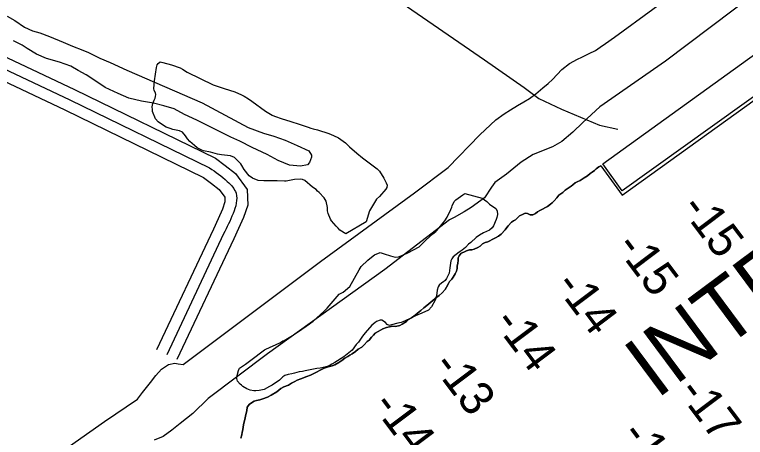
# Model space of a CAD drawing. Extents: x 3683613 to 3738215, y 469626 to 495384.
# Drawn here: x 3688948 to 3689919, y 488310 to 488872 of the extents above; entities that cross this region are included whole.
import ezdxf

# ---------------------------------------------------------------- set-up
doc = ezdxf.new("R2010")
doc.units = 0
for name, color, linetype in [('V-CHAN-DOCK', 7, 'Continuous'), ('V-LEVE-TOET', 7, 'Continuous'), ('V-RIVR-IDEN', 7, 'Continuous'), ('V-ROAD-CNTR', 7, 'Continuous'), ('V-SITE-VEGE', 7, 'Continuous'), ('V-TOPO-SHOR', 7, 'Continuous'), ('V-TOPO-SPOT', 7, 'Continuous')]:
    doc.layers.add(name, color=color, linetype=linetype)

msp = doc.modelspace()

# ---------------------------------------------------------------- linework, layer by layer
at = {"layer": 'V-CHAN-DOCK'}
msp.add_lwpolyline([(3689729.15, 488673.5), (3690051.71, 488906.29), (3690078.78, 488869.56), (3689754.74, 488637.61), (3689729.15, 488673.5)], dxfattribs=at)
at = {"layer": 'V-LEVE-TOET'}
for points in [[(3688803.07, 488145.2), (3689067.59, 488331.33), (3689111.3, 488360.98), (3689118.03, 488369.9), (3689128.56, 488382.87), (3689135.72, 488392.43), (3689143.31, 488400.73), (3689152.6, 488406.92), (3689161.06, 488408.44), (3689165.3, 488407.61), (3689172.08, 488407.01), (3689354.44, 488543.83), (3689479.19, 488635.06), (3689523.94, 488668.31), (3689566.1, 488711.93), (3689586.98, 488731.72), (3689598.16, 488740.03), (3689606.61, 488744.95), (3689616.12, 488750.92), (3689624.35, 488755.62), (3689631.96, 488760.31), (3689640.4, 488766.28), (3689649.68, 488774.37), (3689656.86, 488780.12), (3689662.34, 488785.45), (3689674.78, 488798.64), (3689684.91, 488806.52), (3689695.47, 488812.5), (3689701.39, 488815.28), (3689711.32, 488819.98), (3689719.56, 488824.05), (3689725.68, 488828.31), (3689732.86, 488833.43), (3689744.9, 488841.53), (3689897.29, 488953.44)], [(3689994.12, 488947.11), (3689812.61, 488809.86), (3689725.2, 488749.1), (3689702.85, 488728.23), (3689689.56, 488715.68), (3689674.8, 488703.11), (3689662.54, 488695.85), (3689636.54, 488685.99), (3689620.7, 488675.54), (3689601.5, 488659.56), (3689585.88, 488648.69), (3689581.25, 488642.31), (3689572.21, 488628.08), (3689554.26, 488615.5), (3689545.18, 488609.74), (3689531.66, 488602.05), (3689525.75, 488599.06), (3689439.64, 488533.21), (3689283.85, 488420.87), (3689205.33, 488361.62), (3689184.67, 488341.83), (3689168, 488328.41), (3689157.03, 488319.46), (3689145.42, 488311.36), (3689133.58, 488306.43)]]:
    msp.add_lwpolyline(points, dxfattribs=at)
at = {"layer": 'V-ROAD-CNTR'}
for points in [[(3689142.23, 489278.29), (3689162.29, 489246.61), (3689268.46, 489096.31), (3689365.64, 488967.98), (3689394.38, 488935.92), (3689455.59, 488891.94), (3689572.03, 488811.36), (3689624.73, 488774.96), (3689644.49, 488760.23), (3689674.42, 488746.17), (3689724.72, 488724.8), (3689749.31, 488719.62)], [(3687694.8, 489100.44), (3687788.84, 489167.94), (3687806.27, 489176.37), (3687846.67, 489194.95), (3687889.36, 489212.36), (3687944.11, 489222.38), (3687999.07, 489216.94), (3688049.59, 489205.26), (3688098.64, 489190.05), (3688147.84, 489171.94), (3688197.16, 489153.78), (3688663.75, 488944.15), (3689027.79, 488771.96), (3689214.82, 488680.9), (3689227.8, 488671.05), (3689241.34, 488660.78), (3689257.09, 488639.36), (3689257.63, 488618.59), (3689252.22, 488602.03), (3689245.6, 488587.64), (3689239.31, 488573.98), (3689163.65, 488413.54)], [(3688191.29, 489139.97), (3688657.47, 488930.53), (3689021.3, 488758.43)], [(3688758.88, 488865.97), (3689014.81, 488744.91), (3689199.03, 488655.22), (3689209.67, 488647.15), (3689219.74, 488639.51), (3689227.35, 488629.17), (3689227.51, 488622.99), (3689224.24, 488612.99), (3689218.35, 488600.18), (3689212.12, 488586.65), (3689136.52, 488426.33)], [(3689021.3, 488758.43), (3689206.93, 488668.06)], [(3689225.71, 488580.31), (3689150.08, 488419.93)]]:
    msp.add_lwpolyline(points, dxfattribs=at)
msp.add_spline([(3689206.93, 488668.06), (3689230.54, 488650.14), (3689242.22, 488634.26), (3689238.23, 488607.51), (3689225.71, 488580.31)], degree=3, dxfattribs=at)
at = {"layer": 'V-SITE-VEGE'}
for points in [[(3689303.27, 488732.95), (3689313.45, 488730.04), (3689327.45, 488725.86), (3689337.85, 488722.1), (3689341.45, 488720.64), (3689344.42, 488720.01), (3689350.15, 488718.35), (3689365.42, 488713.54), (3689371.57, 488711.24), (3689378.16, 488707.89), (3689387.72, 488701.15), (3689393.04, 488696.09), (3689402.39, 488687.66), (3689410.05, 488681.56), (3689429.39, 488666.82), (3689432.58, 488663.66), (3689438.35, 488654.37), (3689440.48, 488649.93), (3689441.76, 488648.24), (3689442.84, 488644.86), (3689442.21, 488641.89), (3689441.17, 488639.55), (3689432.74, 488630.2), (3689428.73, 488626.36), (3689419.48, 488611.07), (3689415.1, 488596.44), (3689387.85, 488580.21), (3689380, 488585.26), (3689377.87, 488587.79), (3689375.1, 488590.74), (3689369.14, 488597.49), (3689367.43, 488600.03), (3689364.43, 488607.22), (3689363.78, 488611.03), (3689363.76, 488615.26), (3689361.81, 488623.72), (3689359.04, 488628.16), (3689352.44, 488635.33), (3689350.31, 488637.23), (3689348.4, 488639.12), (3689343.93, 488642.49), (3689333.52, 488651.13), (3689330.33, 488652.59), (3689328, 488653.22), (3689319.74, 488652.76), (3689313.39, 488651.24), (3689308.95, 488650.59), (3689306.62, 488650.58), (3689296.66, 488650.96), (3689283.75, 488650.9), (3689278.87, 488650.66), (3689271.67, 488651.48), (3689263.82, 488654.41), (3689259.57, 488657.35), (3689253.18, 488666), (3689249.97, 488671.28), (3689248.69, 488673.18), (3689242.95, 488679.3), (3689240.18, 488681.62), (3689234.88, 488683.92), (3689223.01, 488685.35), (3689217.71, 488686.38), (3689208.17, 488688.88), (3689198.84, 488690.74), (3689196.72, 488691.58), (3689190.77, 488694.73), (3689187.16, 488697.68), (3689180.78, 488703.16), (3689177.58, 488706.74), (3689175.02, 488710.75), (3689170.98, 488715.61), (3689166.95, 488717.07), (3689158.25, 488718.94), (3689154.65, 488720.19), (3689149.55, 488722.29), (3689141.7, 488727.12), (3689138.72, 488729.22), (3689135.1, 488733.02), (3689131.25, 488742.74), (3689131.02, 488745.71), (3689130.58, 488749.31), (3689131.62, 488753.55), (3689133.5, 488757.79), (3689134.97, 488760.55), (3689135.39, 488762.67), (3689135.59, 488765.43), (3689135.15, 488767.76), (3689133.45, 488770.71), (3689132.8, 488773.25), (3689134.02, 488783.64), (3689136.48, 488801.23), (3689137.31, 488804.83), (3689138.57, 488806.53), (3689141.53, 488809.09), (3689144.92, 488807.83), (3689156.37, 488804.92), (3689168.04, 488800.74), (3689171.23, 488799.06), (3689177.38, 488795.27), (3689211.77, 488778.49), (3689226.41, 488773.48)], [(3689226.41, 488773.48), (3689240.41, 488768.88), (3689249.54, 488764.9), (3689252.94, 488763.22), (3689258.88, 488759.65), (3689263.13, 488756.7), (3689281.2, 488743.44), (3689290.12, 488737.98), (3689293.09, 488736.51), (3689303.27, 488732.95)], [(3689497.62, 488479.06), (3689488.74, 488474.99), (3689480.5, 488471.35), (3689474.16, 488468.36), (3689466.97, 488464.73), (3689463.8, 488463.44), (3689461.26, 488462.58), (3689457.24, 488461.71), (3689448.57, 488459.56), (3689446.03, 488458.7), (3689443.06, 488459.96), (3689440.5, 488462.48), (3689435.83, 488465.64), (3689433.5, 488465.84), (3689428.85, 488464.12), (3689426.32, 488462.42), (3689422.31, 488459.01), (3689413.67, 488448.81), (3689410.3, 488444.34), (3689404.62, 488436.48), (3689401.88, 488433.29), (3689396.41, 488425.85), (3689385.44, 488417.11), (3689373.19, 488409.65), (3689369.6, 488407.3), (3689366, 488405.17), (3689360.3, 488403.23), (3689353.95, 488401.93), (3689349.5, 488401.49), (3689345.06, 488400.83), (3689333.85, 488398.24), (3689330.46, 488397.59), (3689326.01, 488396.93), (3689319.67, 488395.42), (3689316.28, 488394.34), (3689311.21, 488393.47), (3689306.97, 488392.18), (3689304.44, 488390.48), (3689300.01, 488386.22), (3689290.3, 488379.61), (3689286.5, 488377.47), (3689279.31, 488373.84), (3689272.96, 488372.54), (3689268.31, 488371.88), (3689265.98, 488371.87), (3689260.89, 488372.69), (3689256.44, 488374.37), (3689251.34, 488377.52), (3689249.42, 488379.42), (3689247.72, 488380.68), (3689244.1, 488384.69), (3689243.03, 488388.07), (3689243.44, 488390.4), (3689245.31, 488399.1), (3689246.78, 488401.85), (3689254.8, 488407.4), (3689261.98, 488412.52), (3689279.92, 488426.37), (3689281.82, 488427.43), (3689300.21, 488435.78), (3689304.22, 488438.13), (3689306.12, 488438.78), (3689317.1, 488445.39), (3689325.13, 488450.72), (3689339.7, 488460.96), (3689344.55, 488464.58), (3689359.32, 488477.57), (3689363.32, 488481.82), (3689379.12, 488500.32), (3689382.5, 488502.25), (3689384.61, 488503.1), (3689393.48, 488510.34), (3689399.35, 488521.6), (3689405.66, 488532.43), (3689408.39, 488536.89), (3689417.25, 488545.4), (3689422.1, 488549.24), (3689425.9, 488552.65), (3689433.72, 488555.65), (3689439.02, 488553.98), (3689447.51, 488551.05), (3689450.48, 488550.43), (3689453.45, 488549.38), (3689457.89, 488550.04), (3689461.27, 488551.33), (3689470.36, 488555.18), (3689485.15, 488563.09), (3689494.64, 488572.66), (3689503.29, 488580.33), (3689507.3, 488583.52), (3689511.93, 488588.42), (3689517.41, 488595.01), (3689519.52, 488597.77), (3689522.67, 488602.44), (3689527.49, 488612.63), (3689528.75, 488615.82), (3689529.38, 488617.73), (3689531.68, 488623.24), (3689534.21, 488625.8), (3689543.5, 488632.19), (3689546.04, 488634.11)], [(3689546.04, 488634.11), (3689569.15, 488627.86), (3689575.1, 488623.23), (3689578.93, 488619.86), (3689587.22, 488614.18), (3689589.14, 488611.01), (3689589.37, 488606.14), (3689588.54, 488601.9), (3689587.71, 488599.36), (3689584.15, 488590.87), (3689582.46, 488588.53), (3689578.67, 488585.34), (3689570.85, 488581.7), (3689565.56, 488578.71), (3689560.92, 488575.51), (3689553.96, 488569.13), (3689551.01, 488566.57), (3689546.79, 488562.1), (3689544.89, 488560.4), (3689542.57, 488558.9), (3689538.35, 488555.92), (3689530.33, 488549.74), (3689528.64, 488547.19), (3689527.39, 488544.43), (3689525.95, 488535.11), (3689525.14, 488528.11), (3689521.56, 488521.11), (3689519.89, 488518.35), (3689517.77, 488516.64), (3689515.66, 488515.15), (3689511.87, 488512.17), (3689510.6, 488510.25), (3689509.14, 488505.59), (3689508.33, 488497.96), (3689506.45, 488492.23), (3689501.83, 488483.53), (3689497.62, 488479.06)]]:
    msp.add_lwpolyline(points, dxfattribs=at)
at = {"layer": 'V-TOPO-SHOR'}
for points in [[(3688938.41, 488869.51), (3688948.6, 488863.62), (3688961.35, 488855), (3688971.75, 488850.18), (3688981.51, 488847.26), (3688994.45, 488842.45), (3689012.7, 488834.91), (3689025.01, 488829.88), (3689038.8, 488824.44), (3689046.23, 488821.29), (3689061.3, 488813.95), (3689075.09, 488808.08), (3689097.17, 488797.6), (3689197.13, 488754.22), (3689258.28, 488721.88), (3689278.65, 488714.35), (3689292.44, 488710.18), (3689307.5, 488704.74), (3689323.42, 488697.83), (3689338.91, 488690.7), (3689342.54, 488684.79), (3689342.55, 488682.24), (3689339.83, 488675.24), (3689337.09, 488672.27), (3689327.99, 488670.32), (3689313.16, 488671.73), (3689298.09, 488678.01), (3689283.65, 488685.78), (3689263.49, 488695.01), (3689247.35, 488703.41), (3689235.47, 488708.86), (3689212.96, 488719.98), (3689190.04, 488731.31), (3689173.69, 488738.86), (3689160.1, 488746.63), (3689146.31, 488750.59), (3689132.53, 488753.92), (3689116.85, 488756.6), (3689099.67, 488760.54), (3689085.45, 488766.62), (3689068.47, 488775.01), (3689055.94, 488783), (3689042.98, 488791.63), (3689032.57, 488797.51), (3689022.8, 488803.18), (3689007.95, 488808.62), (3688990.56, 488813.41), (3688977.19, 488819.07), (3688964.87, 488826.42), (3688958.07, 488830.84), (3688946.82, 488836.93)], [(3689498.39, 488487.42), (3689503.45, 488491.89), (3689506.2, 488494.02), (3689508.94, 488496.36), (3689511.89, 488498.49), (3689515.9, 488502.11), (3689519.9, 488506.58), (3689521.58, 488509.77), (3689524.1, 488514.44), (3689525.79, 488516.99), (3689528.53, 488520.17), (3689530.42, 488522.72), (3689533.36, 488527.4), (3689535.04, 488531.01), (3689535.66, 488534.4), (3689535.86, 488537.58), (3689536.69, 488541.39), (3689537.31, 488545), (3689537.08, 488548.6), (3689538.55, 488551.35), (3689541.29, 488554.55), (3689544.88, 488556.04), (3689548.26, 488557.97), (3689552.07, 488559.04), (3689555.24, 488559.27), (3689558.21, 488559.92), (3689563.28, 488562.06), (3689566.23, 488564.19), (3689569.61, 488567.17), (3689573.2, 488568.88), (3689576.37, 488569.75), (3689579.33, 488571.24), (3689582.5, 488572.95), (3689586.52, 488575.09), (3689590.53, 488577.44), (3689594.12, 488579.78), (3689599.39, 488585.74), (3689601.7, 488588.93), (3689603.6, 488591.27), (3689607.81, 488595.73), (3689610.56, 488597.65), (3689613.3, 488599.15), (3689616.04, 488601.7), (3689618.79, 488604.26), (3689622.59, 488606.18), (3689625.97, 488607.89), (3689629.15, 488607.48), (3689632.97, 488605.59), (3689636.36, 488605.61), (3689639.74, 488607.32), (3689642.48, 488609.45), (3689645.65, 488611.37), (3689649.03, 488613.29), (3689653.05, 488615.43), (3689656, 488616.92), (3689659.8, 488619.7), (3689662.12, 488621.61), (3689664.44, 488624.38), (3689668.24, 488628.21), (3689670.98, 488631.61), (3689673.29, 488633.74), (3689676.04, 488635.44), (3689679.42, 488638.43), (3689681.95, 488640.34), (3689687.02, 488643.76), (3689689.55, 488645.46), (3689692.5, 488648.02), (3689695.25, 488649.51), (3689699.05, 488651.44), (3689701.8, 488652.93), (3689704.54, 488654.64), (3689708.98, 488657.41), (3689712.57, 488660.4), (3689715.31, 488662.53), (3689718.05, 488664.45), (3689720.59, 488666.79), (3689723.96, 488669.35), (3689726.71, 488670.63), (3689755.06, 488631.58), (3690082.89, 488867.78)], [(3689726.71, 488670.63), (3689723.96, 488669.35), (3689720.59, 488666.79), (3689718.05, 488664.45), (3689715.31, 488662.53), (3689712.57, 488660.4), (3689708.98, 488657.41), (3689704.54, 488654.64), (3689701.8, 488652.93), (3689699.05, 488651.44), (3689695.25, 488649.51), (3689692.5, 488648.02), (3689689.55, 488645.46), (3689687.02, 488643.76), (3689681.95, 488640.34), (3689679.42, 488638.43), (3689676.04, 488635.44), (3689673.29, 488633.74), (3689670.98, 488631.61), (3689668.24, 488628.21), (3689664.44, 488624.38), (3689662.12, 488621.61), (3689659.8, 488619.7), (3689656, 488616.92), (3689653.05, 488615.43), (3689649.03, 488613.29), (3689645.65, 488611.37), (3689642.48, 488609.45), (3689639.74, 488607.32), (3689636.36, 488605.61), (3689632.97, 488605.59), (3689629.15, 488607.48), (3689625.97, 488607.89), (3689622.59, 488606.18), (3689618.79, 488604.26), (3689616.04, 488601.7), (3689613.3, 488599.15), (3689610.56, 488597.65), (3689607.81, 488595.73), (3689603.6, 488591.27), (3689601.7, 488588.93), (3689599.39, 488585.74), (3689594.12, 488579.78), (3689590.53, 488577.44), (3689586.52, 488575.09), (3689582.5, 488572.95), (3689579.33, 488571.24), (3689576.37, 488569.75), (3689573.2, 488568.88), (3689569.61, 488567.17), (3689566.23, 488564.19), (3689563.28, 488562.06), (3689558.21, 488559.92), (3689555.24, 488559.27), (3689552.07, 488559.04), (3689548.26, 488557.97), (3689544.88, 488556.04), (3689541.29, 488554.55), (3689538.55, 488551.35), (3689537.08, 488548.6), (3689537.31, 488545), (3689536.69, 488541.39), (3689535.86, 488537.58), (3689535.66, 488534.4), (3689535.04, 488531.01), (3689533.36, 488527.4), (3689530.42, 488522.72), (3689528.53, 488520.17), (3689525.79, 488516.99), (3689524.1, 488514.44), (3689521.58, 488509.77), (3689519.9, 488506.58), (3689515.9, 488502.11), (3689511.89, 488498.49), (3689508.94, 488496.36), (3689506.2, 488494.02), (3689503.45, 488491.89), (3689498.39, 488487.42), (3689495.65, 488485.08), (3689491.64, 488482.09), (3689487.63, 488478.68), (3689485.31, 488476.77), (3689480.03, 488472.51), (3689474.97, 488468.88), (3689471.38, 488466.54), (3689468.42, 488464.19), (3689462.93, 488460.35), (3689459.55, 488458.85), (3689454.05, 488457.35), (3689450.23, 488457.96), (3689446, 488456.89), (3689442.2, 488456.02), (3689436.91, 488454.09), (3689430.78, 488450.89), (3689426.77, 488448.33), (3689424.66, 488445.99), (3689422.14, 488443.22), (3689418.77, 488439.18), (3689416.44, 488437.26), (3689412.23, 488432.8), (3689409.06, 488430.03)], [(3689248.66, 488309.19), (3689249.91, 488313.43), (3689250.53, 488317.04), (3689251.15, 488320.22), (3689251.76, 488324.24), (3689252.38, 488329.12), (3689253.21, 488332.09), (3689254.25, 488336.11), (3689255.08, 488340.35), (3689256.33, 488345.44), (3689256.94, 488350.11), (3689260.1, 488354.15), (3689266.43, 488357.99), (3689269.39, 488359.27), (3689273.83, 488360.14), (3689277.85, 488361.22), (3689283.77, 488363.57), (3689288.64, 488365.93), (3689296.24, 488370.41), (3689301.51, 488374.88), (3689305.53, 488377.02), (3689311.66, 488379.59), (3689315.67, 488381.94), (3689320.32, 488384.5), (3689323.49, 488386), (3689328.14, 488387.93), (3689336.39, 488391.14), (3689341.04, 488392.86), (3689343.78, 488394.14), (3689348.01, 488396.28), (3689354.56, 488399.7), (3689359.42, 488401.84), (3689363.02, 488403.34), (3689366.19, 488404.2), (3689369.78, 488405.28), (3689373.38, 488406.56), (3689378.87, 488409.55), (3689382.88, 488412.33), (3689386.68, 488415.31), (3689390.48, 488417.45), (3689393.44, 488419.15), (3689396.19, 488420.86), (3689400.83, 488424.06), (3689404.42, 488427.04), (3689409.06, 488430.03), (3689412.23, 488432.8), (3689416.44, 488437.26), (3689418.77, 488439.18), (3689422.14, 488443.22), (3689424.66, 488445.99), (3689426.77, 488448.33), (3689430.78, 488450.89), (3689436.91, 488454.09), (3689442.2, 488456.02), (3689446, 488456.89), (3689450.23, 488457.96), (3689454.05, 488457.35), (3689459.55, 488458.85), (3689462.93, 488460.35), (3689468.42, 488464.19), (3689471.38, 488466.54), (3689474.97, 488468.88), (3689480.03, 488472.51), (3689485.31, 488476.77), (3689487.63, 488478.68), (3689491.64, 488482.09), (3689495.65, 488485.08), (3689498.39, 488487.42)], [(3689409.06, 488430.03), (3689404.42, 488427.04), (3689400.83, 488424.06), (3689396.19, 488420.86), (3689393.44, 488419.15), (3689390.48, 488417.45), (3689386.68, 488415.31), (3689382.88, 488412.33), (3689378.87, 488409.55), (3689373.38, 488406.56), (3689369.78, 488405.28), (3689366.19, 488404.2), (3689363.02, 488403.34), (3689359.42, 488401.84), (3689354.56, 488399.7), (3689348.01, 488396.28), (3689343.78, 488394.14), (3689341.04, 488392.86), (3689336.39, 488391.14), (3689328.14, 488387.93), (3689323.49, 488386), (3689320.32, 488384.5), (3689315.67, 488381.94), (3689311.66, 488379.59), (3689305.53, 488377.02), (3689301.51, 488374.88), (3689296.24, 488370.41), (3689288.64, 488365.93), (3689283.77, 488363.57), (3689277.85, 488361.22), (3689273.83, 488360.14), (3689269.39, 488359.27), (3689266.43, 488357.99), (3689260.1, 488354.15), (3689256.94, 488350.11), (3689256.33, 488345.44), (3689255.08, 488340.35), (3689254.25, 488336.11), (3689253.21, 488332.09), (3689252.38, 488329.12), (3689251.76, 488324.24), (3689251.15, 488320.22), (3689250.53, 488317.04), (3689249.91, 488313.43), (3689248.66, 488309.19)]]:
    msp.add_lwpolyline(points, dxfattribs=at)

# ---------------------------------------------------------------- texts
at = {"layer": 'V-RIVR-IDEN'}
msp.add_text('INTRACOASTAL WATERWAY (ALTERNATE ROUTE)', height=82.9998, rotation=36.61505, dxfattribs=at).set_placement((3689800.26, 488359.88))
at = {"layer": 'V-TOPO-SPOT'}
for s, p in [('-15', (3689831.37, 488614.4)), ('-15', (3689744.94, 488563.19)), ('-14', (3689664.24, 488511.98)), ('-14', (3689582.89, 488462.82)), ('-13', (3689501.58, 488405.07)), ('-17', (3689827.78, 488370.21)), ('-14', (3689421.69, 488352.42)), ('-17', (3689751.92, 488313.37))]:
    msp.add_text(s, height=45, rotation=306.93473, dxfattribs=at).set_placement(p)

doc.saveas('drawing.dxf')
